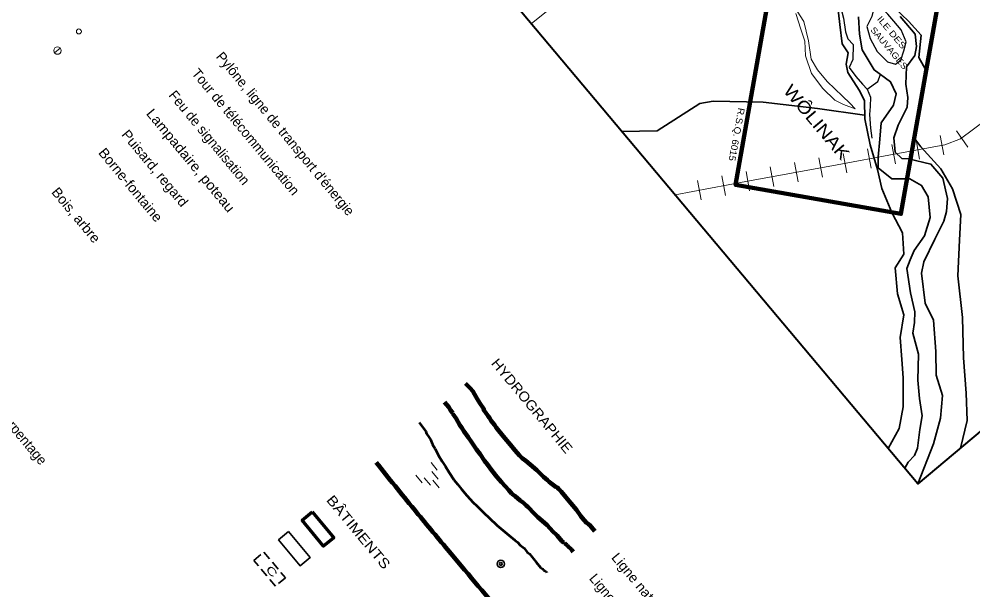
# Model space of a CAD drawing. Extents: x 386081 to 389416, y 5130568 to 5134082.
# Drawn here: x 388259.3 to 388645.6, y 5131075.7 to 5131306.8 of the extents above; entities that cross this region are included whole.
import ezdxf
from ezdxf.enums import TextEntityAlignment as Align

# ---------------------------------------------------------------- set-up
doc = ezdxf.new("R2010")
doc.units = 0
doc.header["$LTSCALE"] = 1.2
for name, pattern in [('DASH_DOUBLE_DOT', [9.2, 5, -1.2, 0.3, -1.2, 0.3, -1.2]), ('LONG_DASHED', [7.5, 6, -1.5]), ('MEDIUM_DASHED', [4.5, 3, -1.5])]:
    doc.linetypes.add(name, pattern=pattern)
for name, color, linetype, lineweight in [('10', 7, 'Continuous', 35), ('31', 7, 'Continuous', 70), ('36', 7, 'Continuous', 13), ('4', 7, 'DASH_DOUBLE_DOT', 53), ('6', 7, 'Continuous', 13), ('63', 7, 'Continuous', 13)]:
    doc.layers.add(name, color=color, linetype=linetype, lineweight=lineweight)

msp = doc.modelspace()

# ---------------------------------------------------------------- linework, layer by layer
at = {"layer": '10'}
for radius in [1.5, 0.6]:
    msp.add_circle((388454.437, 5131086.194), radius, dxfattribs=at)
at = {"layer": '31'}
msp.add_lwpolyline([(388378.06, 5131107.27), (388386.76, 5131096.78), (388382.69, 5131093.41), (388374.03, 5131103.91)], close=True, dxfattribs=at)
at = {"layer": '31', "lineweight": 35}
msp.add_lwpolyline([(388368.45, 5131099.25), (388377.18, 5131088.76), (388373.14, 5131085.44), (388364.43, 5131095.9)], close=True, dxfattribs=at)
at = {"layer": '31', "linetype": 'MEDIUM_DASHED', "lineweight": 35}
msp.add_lwpolyline([(388358.47, 5131090.99), (388367.18, 5131080.49), (388363.14, 5131077.15), (388354.45, 5131087.62)], close=True, dxfattribs=at)
at = {"layer": '36'}
msp.add_line((388273.74, 5131293.11), (388276.04, 5131295), dxfattribs=at)
for centre, radius in [((388283.572, 5131301.813), 1), ((388274.889, 5131294.061), 1.5)]:
    msp.add_circle(centre, radius, dxfattribs=at)
at = {"layer": '4', "linetype": 'Continuous', "lineweight": 90}
msp.add_lwpolyline([(388440.16, 5131159.29), (388442.04, 5131157.34), (388443.04, 5131156.14), (388443.73, 5131154.98), (388444.83, 5131152.99), (388445.93, 5131151.31), (388447.48, 5131149.13), (388447.74, 5131148.18), (388448.03, 5131147.84), (388449.3, 5131145.98), (388449.87, 5131145.31), (388450.55, 5131144.13), (388451.82, 5131142.56), (388452.52, 5131141.42), (388453.67, 5131140.03), (388456.08, 5131137.13), (388458.35, 5131134.35), (388460.07, 5131132.3), (388461.93, 5131130.07), (388463.08, 5131128.99), (388464.54, 5131127.89), (388466.29, 5131126.43), (388469.05, 5131124.12), (388471.77, 5131121.44), (388473.37, 5131120.15), (388473.97, 5131119.48), (388474.7, 5131118.94), (388476.89, 5131117.27), (388477.19, 5131117.23), (388477.75, 5131116.53), (388478.49, 5131115.96), (388478.91, 5131115.47), (388480.77, 5131113.24), (388482.77, 5131110.83), (388485.05, 5131108.1), (388486.88, 5131105.56), (388487.44, 5131104.87), (388489.17, 5131102.79), (388489.61, 5131102.58), (388489.89, 5131102.23), (388490.64, 5131101.68), (388491.07, 5131101.2), (388492.48, 5131099.44)], dxfattribs=at)
at = {"layer": '4', "linetype": 'LONG_DASHED', "lineweight": 90}
msp.add_lwpolyline([(388431.66, 5131151.69), (388433.36, 5131149.64), (388434.06, 5131148.47), (388435.04, 5131147.26), (388435.01, 5131146.94), (388436.31, 5131145.12), (388437.81, 5131142.31), (388438.65, 5131141.29), (388439.47, 5131139.93), (388441.17, 5131137.57), (388442.74, 5131135.37), (388444.55, 5131132.54), (388446.12, 5131130.64), (388447.76, 5131127.95), (388449.05, 5131126.42), (388450.78, 5131124.06), (388452.88, 5131121.46), (388454.75, 5131119.23), (388457.61, 5131116.1), (388458.89, 5131114.57), (388460.2, 5131113.64), (388462.23, 5131111.84), (388463.56, 5131110.9), (388464.7, 5131109.81), (388465.43, 5131109.29), (388466, 5131108.59), (388467.43, 5131107.17), (388469.48, 5131105.09), (388471.21, 5131103.63), (388473.23, 5131101.82), (388475.53, 5131099.38), (388476.98, 5131097.99), (388477.25, 5131097.65), (388479.11, 5131095.41), (388479.85, 5131094.86), (388480.16, 5131094.8), (388480.42, 5131094.47), (388481.31, 5131093.74), (388481.59, 5131093.42), (388483.01, 5131091.98), (388483.32, 5131091.62), (388483.74, 5131091.13)], dxfattribs=at)
at = {"layer": '4'}
msp.add_lwpolyline([(388421.39, 5131143.39), (388424.09, 5131139.84), (388424.33, 5131138.86), (388424.9, 5131138.2), (388426.02, 5131136.51), (388426.8, 5131134.55), (388427.78, 5131132.73), (388429.14, 5131130.1), (388430.67, 5131127.63), (388432.07, 5131125.6), (388433.45, 5131123.26), (388435.58, 5131120.09), (388436.85, 5131118.54), (388438.54, 5131116.47), (388440.69, 5131113.88), (388443.25, 5131111.1), (388444.72, 5131109.68), (388447.61, 5131106.85), (388449.76, 5131104.91), (388452.92, 5131101.72), (388454.54, 5131100.45), (388457.87, 5131097.71), (388460.04, 5131095.74), (388461.23, 5131094.97), (388462.21, 5131093.79), (388463.83, 5131092.51), (388465.12, 5131090.98), (388465.69, 5131090.59), (388465.99, 5131090.23), (388468.68, 5131086.96), (388470.53, 5131084.75), (388471.26, 5131084.22), (388471.72, 5131083.67), (388472.15, 5131083.48), (388472.89, 5131082.92), (388473.03, 5131082.75)], dxfattribs=at)
at = {"layer": '4', "linetype": 'Continuous', "lineweight": 140}
msp.add_spline([(388403.93, 5131127.31), (388419.31, 5131108.29), (388432.89, 5131091.97), (388454.98, 5131065.71)], degree=3, dxfattribs=at)
at = {"layer": '6'}
for p, q in [((388426.16, 5131127.23), (388428.71, 5131124.16)), ((388420.02, 5131122.12), (388422.56, 5131119.06)), ((388423.45, 5131121.08), (388426.01, 5131118.04)), ((388426.53, 5131123.65), (388429.1, 5131120.57)), ((388426.91, 5131120.07), (388429.48, 5131116.99))]:
    msp.add_line(p, q, dxfattribs=at)
at = {"layer": '63'}
for p, q in [((388633.86, 5131251.86), (388632.4, 5131259.73)), ((388643.53, 5131254.95), (388639, 5131261.54)), ((388614.2, 5131248.21), (388612.74, 5131256.08)), ((388624.03, 5131250.04), (388622.57, 5131257.91)), ((388594.53, 5131244.56), (388593.07, 5131252.43)), ((388604.36, 5131246.39), (388602.9, 5131254.26)), ((388574.87, 5131240.92), (388573.41, 5131248.79)), ((388584.7, 5131242.74), (388583.24, 5131250.61)), ((388555.2, 5131237.27), (388553.74, 5131245.14)), ((388565.03, 5131239.09), (388563.57, 5131246.96)), ((388535.54, 5131233.62), (388534.08, 5131241.49)), ((388545.37, 5131235.44), (388543.91, 5131243.31))]:
    msp.add_line(p, q, dxfattribs=at)
at = {"layer": '63', "lineweight": 25}
msp.add_line((388623.34, 5131118.57), (388617.97, 5131124.97), dxfattribs=at)
at = {"layer": '63', "lineweight": 35}
msp.add_line((388623.34, 5131118.57), (388617.97, 5131124.97), dxfattribs=at)
at = {"layer": '63', "lineweight": 40}
msp.add_lwpolyline([(388592.16, 5131539.51), (388812.37, 5131277.36), (388623.34, 5131118.57), (388403.13, 5131380.72)], close=True, dxfattribs=at)
at = {"layer": '63'}
for points in [[(388524.99, 5131235.66), (388553.61, 5131241.09), (388590.57, 5131247.86), (388613.67, 5131252.16), (388634.24, 5131255.95), (388640.61, 5131258.33), (388676.35, 5131284.85), (388689.02, 5131300.62), (388695.01, 5131310.51), (388709.35, 5131331.99), (388714.85, 5131354.68), (388718.09, 5131366.57), (388721.77, 5131373.44), (388727.23, 5131375.6), (388729.87, 5131375.58)], [(388448.5, 5131326.71), (388466.78, 5131304.95), (388475.65, 5131312.1)], [(388573.86, 5131309.08), (388575.89, 5131302.77), (388577.56, 5131297.94), (388577.85, 5131291.95), (388580.29, 5131284.79), (388584.77, 5131278.76), (388589.68, 5131273.97), (388593.24, 5131272.21), (388597.93, 5131270.51), (388595.71, 5131272.8), (388592.73, 5131275.65), (388586.62, 5131281.5), (388582.67, 5131286.2), (388580.15, 5131290.62), (388579.02, 5131297.98), (388577.13, 5131305.89), (388573.29, 5131311.87)]]:
    msp.add_lwpolyline(points, dxfattribs=at)
at = {"layer": '63', "lineweight": 158}
msp.add_lwpolyline([(388634.46, 5131330.34), (388616.46, 5131227.91), (388549.49, 5131239.68), (388567.5, 5131342.11)], close=True, dxfattribs=at)
at = {"layer": '63', "lineweight": 35}
for points in [[(388640.59, 5131133.06), (388643.3, 5131144.23), (388642.91, 5131155.28), (388641.85, 5131169.67), (388641.34, 5131185.95), (388639.53, 5131202.91), (388640.21, 5131217.35), (388640.73, 5131227.74), (388637.38, 5131238.08), (388632.68, 5131246.22), (388624.56, 5131255.04), (388622.15, 5131258.34), (388624.05, 5131271.32), (388626.86, 5131285.76), (388623.67, 5131291.25), (388624.64, 5131300.25), (388619.53, 5131305.91), (388613.83, 5131311.43), (388610.92, 5131315.74), (388612.19, 5131321.43), (388613.46, 5131327.12), (388615.65, 5131330.02), (388617.51, 5131333.72)], [(388590.67, 5131314.02), (388591.78, 5131304.65), (388592.65, 5131296.84), (388595.03, 5131293.16), (388594.24, 5131288.59), (388594.92, 5131285.24), (388599.51, 5131278.08), (388601.65, 5131273.84), (388601.78, 5131266.48), (388603.95, 5131255.86), (388606.95, 5131245.94), (388608.79, 5131238.24), (388612.76, 5131228.43), (388617.08, 5131220.32), (388617.67, 5131211.57), (388614.1, 5131206.09), (388615.12, 5131195.56), (388617.66, 5131187.03), (388616.09, 5131177.89), (388616.85, 5131168.94), (388617.37, 5131161.55), (388617.31, 5131149.76), (388615.77, 5131141.01), (388611.26, 5131132.95)], [(388617.97, 5131124.97), (388619.36, 5131127.37), (388621.93, 5131130.13), (388623.18, 5131133.01), (388624.17, 5131140.56), (388624.99, 5131146.13), (388623.94, 5131153.2), (388623.26, 5131160.56), (388623.52, 5131171.16), (388621.27, 5131179.66), (388621.98, 5131183.91), (388622.02, 5131188.22), (388620.38, 5131196), (388618.9, 5131205.76), (388620.21, 5131209.3), (388621.87, 5131213.14), (388626.04, 5131219.08), (388628.35, 5131226.52), (388627.42, 5131234.9), (388624.83, 5131239.44), (388620.09, 5131242.17), (388612.78, 5131242.14), (388607.2, 5131246.61), (388607.24, 5131250.92), (388607.87, 5131258.17), (388608.45, 5131264.76), (388613.39, 5131271.97), (388614.46, 5131276.53), (388612.22, 5131281.37), (388605.68, 5131286.25), (388600.74, 5131294.31), (388599.64, 5131300.72), (388599.25, 5131307.72)], [(388616.2, 5131307.91), (388622.22, 5131300.75), (388622.77, 5131295.72), (388622.13, 5131292.13), (388618.73, 5131287.44), (388618.46, 5131280.49), (388619.31, 5131275.11), (388618.97, 5131271.15), (388615.34, 5131263.83), (388613.56, 5131258.67), (388614.06, 5131252.99), (388616.83, 5131250.42), (388619.46, 5131250.2), (388628.57, 5131248.08), (388633.39, 5131242.35), (388635.33, 5131234.21), (388634.87, 5131228.94), (388633.87, 5131225.04), (388630.24, 5131217.72), (388625.78, 5131208.48), (388624.72, 5131203.92), (388626.32, 5131191.83), (388629.7, 5131184.9), (388630.58, 5131172.21), (388630.74, 5131162.57), (388633.34, 5131154.37), (388632.54, 5131145.15), (388629.64, 5131134.77), (388623.34, 5131118.57)], [(388503.41, 5131261.34), (388517.68, 5131261.59), (388535.07, 5131272.65), (388540.37, 5131273.54), (388560.63, 5131273.14), (388582.63, 5131270.65), (388601.75, 5131267.92)]]:
    msp.add_lwpolyline(points, dxfattribs=at)
at = {"layer": '63', "lineweight": 25}
for points in [[(388594.57, 5131325.07), (388595.66, 5131318.49), (388592.84, 5131315.83), (388591.78, 5131312.85), (388593.22, 5131307.24), (388594.03, 5131301.68), (388594.91, 5131298.86), (388597.14, 5131296.57), (388596.92, 5131290.45), (388595.51, 5131287.18), (388598.26, 5131283.56), (388600.89, 5131280.42), (388602.82, 5131278.48), (388604.14, 5131275.14), (388603.98, 5131271.44), (388603.7, 5131268.23), (388604.19, 5131262.7), (388604.64, 5131258.63)], [(388617.97, 5131124.97), (388619.36, 5131127.37), (388621.93, 5131130.13), (388623.18, 5131133.01), (388624.17, 5131140.56), (388624.99, 5131146.13), (388623.94, 5131153.2), (388623.26, 5131160.56), (388623.52, 5131171.16), (388621.27, 5131179.66), (388621.98, 5131183.91), (388622.02, 5131188.22), (388620.38, 5131196), (388618.9, 5131205.76), (388620.21, 5131209.3), (388621.87, 5131213.14), (388626.04, 5131219.08), (388628.35, 5131226.52), (388627.42, 5131234.9), (388624.83, 5131239.44), (388620.09, 5131242.17), (388612.78, 5131242.14), (388607.2, 5131246.61), (388607.24, 5131250.92), (388607.87, 5131258.17), (388608.45, 5131264.76), (388613.39, 5131271.97), (388614.46, 5131276.53), (388612.22, 5131281.37), (388605.68, 5131286.25), (388600.74, 5131294.31), (388599.64, 5131300.72), (388599.25, 5131307.72)], [(388616.2, 5131307.91), (388622.22, 5131300.75), (388622.77, 5131295.72), (388622.13, 5131292.13), (388618.73, 5131287.44), (388618.46, 5131280.49), (388619.31, 5131275.11), (388618.97, 5131271.15), (388615.34, 5131263.83), (388613.56, 5131258.67), (388614.06, 5131252.99), (388616.83, 5131250.42), (388619.46, 5131250.2), (388628.57, 5131248.08), (388633.39, 5131242.35), (388635.33, 5131234.21), (388634.87, 5131228.94), (388633.87, 5131225.04), (388630.24, 5131217.72), (388625.78, 5131208.48), (388624.72, 5131203.92), (388626.32, 5131191.83), (388629.7, 5131184.9), (388630.58, 5131172.21), (388630.74, 5131162.57), (388633.34, 5131154.37), (388632.54, 5131145.15), (388629.64, 5131134.77), (388623.34, 5131118.57)], [(388602.85, 5131278.41), (388607.12, 5131281.5), (388608.14, 5131284.41)]]:
    msp.add_lwpolyline(points, dxfattribs=at)
msp.add_lwpolyline([(388606, 5131313.69), (388604.62, 5131307.88), (388602.71, 5131303.77), (388604.04, 5131299), (388606.88, 5131293.7), (388610.98, 5131289.46), (388614.21, 5131288.59), (388616.48, 5131290.15), (388617.69, 5131294.02), (388618.59, 5131297.64), (388616.49, 5131302.48), (388613.58, 5131305.94), (388611.21, 5131308.77), (388608.34, 5131311.54)], close=True, dxfattribs=at)

# ---------------------------------------------------------------- texts
at = {"layer": '31', "width": 1.6}
msp.add_text('C', height=2.999, rotation=309.645, dxfattribs=at).set_placement((388359.03, 5131083.98))
at = {"layer": '63'}
for s, height, rotation, width, p in [('ILE DES', 2.5, 310.029, 1.25, (388606.59, 5131306.72)), ('SAUVAGES', 2.5, 310.029, 1.15, (388603.91, 5131302.36)), ('WÔLINAK', 5, 310.029, 1.2, (388568.52, 5131277.66)), ('Lampadaire, poteau', 4, 309.645, 1.1, (388310.58, 5131268.45)), ('Puisard, regard', 4, 309.645, 1.05, (388300.57, 5131259.93)), ('Borne-fontaine', 4, 309.645, 1.05, (388291.22, 5131252.57)), ('Bois, arbre', 4, 309.645, 1.05, (388272.23, 5131236.62)), ('Ligne naturelle des hautes eaux', 4, 309.645, 1.05, (388498.95, 5131088.65))]:
    msp.add_text(s, height=height, rotation=rotation, dxfattribs=dict(at, width=width)).set_placement(p)
for s, p in [("Pylône, ligne de transport d'énergie", (388338.84, 5131291.45)), ('Tour de télécommunication', (388328.99, 5131284.74)), ('Feu de signalisation', (388319.69, 5131275.86)), ("Limite d'occupation ou d'arpentage", (388215.23, 5131189.46)), ('Ligne naturelle des hautes eaux non-définie', (388489.99, 5131080.19))]:
    msp.add_text(s, height=4, rotation=309.645, dxfattribs=at).set_placement(p)
for s, height, rotation, width, p in [('R.S.Q. 6015', 2.69, 259.632, 1.1, (388548.64, 5131260.337)), ('HYDROGRAPHIE', 4, 309.645, 1.1, (388465.508, 5131148.926)), ('BÂTIMENTS', 4, 309.645, 1.2, (388395.255, 5131097.796))]:
    msp.add_text(s, height=height, rotation=rotation, dxfattribs=dict(at, width=width)).set_placement(p, align=Align.CENTER)

doc.saveas('drawing.dxf')
